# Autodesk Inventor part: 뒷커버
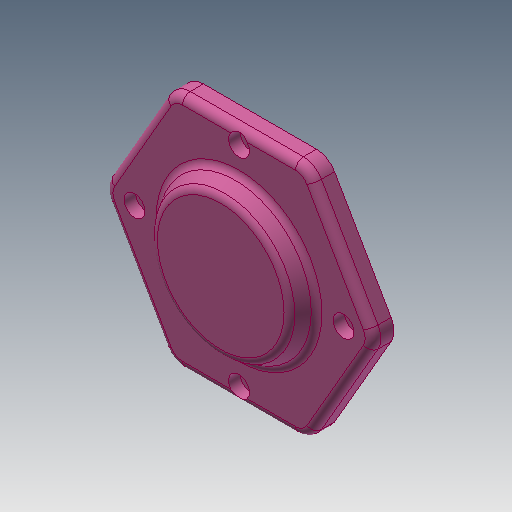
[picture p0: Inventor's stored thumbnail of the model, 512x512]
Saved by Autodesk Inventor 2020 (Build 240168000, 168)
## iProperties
Created: 2013-02
Part Number: 뒷커버
Document SubType Name: Modeling
Density: 1 g/cm^3
Material: 일반
Appearance: 분홍색
Author: 한국산업디자인학원[gmhk.co.kr]
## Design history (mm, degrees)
sketch "스케치1" dims "d37" = 105
  geometry: L1 (50.191, -4)-(28.559, -41.466); L2 (21.631, -45.466)-(-21.631, -45.466); L3 (-28.559, -41.466)-(-50.191, -4); L4 (-50.191, 4)-(-28.559, 41.466); L5 (-21.631, 45.466)-(21.631, 45.466); L6 (28.559, 41.466)-(50.191, 4); C1 r 30 at (0, 0); A1 r 8 centre (-21.631, 37.466) between (-21.631, 45.466) and (-28.559, 41.466); A2 r 8 centre (21.631, 37.466) between (28.559, 41.466) and (21.631, 45.466); A3 r 8 centre (43.262, 0) between (50.191, -4) and (50.191, 4); A4 r 8 centre (21.631, -37.466) between (21.631, -45.466) and (28.559, -41.466); A5 r 8 centre (-21.631, -37.466) between (-28.559, -41.466) and (-21.631, -45.466); A6 r 8 centre (-43.262, 0) between (-50.191, 4) and (-50.191, -4); 9 further points
  constraints: 12 end point, 12 point on circle, 12 point on line, 12 tangent, 7 centre point, 5 equal radius, 3 coincident, 1 horizontal, 1 horizontal alignment, 15 other
  dimensions: "d39" = 60 diameter of C1; "d40" = 8 radius of A1
extrude "돌출1" new body sketch "스케치1" distance "d0" = 8; taper "d1" = 0 deg
sketch "스케치2"
  geometry: C1 r 30 at (0, 0); 1 further point
  constraints: 1 centre point, 1 coincident
  dimensions: "d2" = 60 diameter of C1
extrude "돌출2" join sketch "스케치2" distance "d3" = 7; taper "d4" = -30 deg
sketch "스케치3"
  geometry: C1 r 30 at (0, 0) reference; A1 r 40 centre (0, 0) between (0, 40) and (-40, 0); 2 further points
  constraints: 4 point on circle, 2 horizontal alignment, 2 vertical alignment, 1 centre point, 1 coincident
  dimensions: "d47" = 80 diameter of A1
hole "구멍2" sketch "스케치3" at (0, 40), (-40, 0), (0, -40), (40, 0) diameter "d14" = 4.5; stored, may be unused: countersink angle "d18" = 90 deg, drill point angle "d20" = 118 deg; dims "d15" = 6, "d16" = 8, "d17" = 4.4, "d19" = 20
extrude "돌출3" join sketch "스케치1" distance "d21" = 12; taper "d22" = 0 deg
hole "구멍3" diameter "d25" = 30; stored, may be unused: countersink angle "d29" = 90 deg, drill point angle "d31" = 0 deg; dims "d26" = 6, "d27" = 42, "d28" = 13, "d30" = 16, "d50" = 10, "d51" = 10
fillet "모깎기1" dims "d32" = 3, "d33" = 1
chamfer "모따기1" distance "d34" = 1; stored, may be unused: second distance "d35" = 2, angle "d36" = 45 deg
chamfer "모따기2" distance "d43" = 1; stored, may be unused: second distance "d44" = 2, angle "d45" = 45 deg
fillet "모깎기2" dims "d46" = 3
node "솔리드1"
